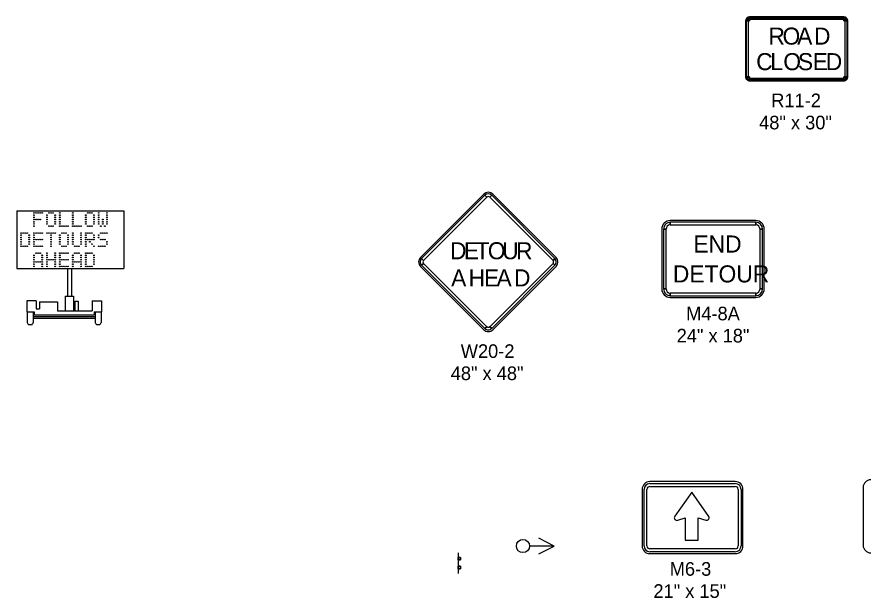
# Model space of a CAD drawing. Extents: x 10133 to 81668, y 6132 to 11018.
# Drawn here: x 10465.2 to 10961.7, y 6745 to 7086.2 of the extents above; entities that cross this region are included whole.
import ezdxf

# ---------------------------------------------------------------- set-up
doc = ezdxf.new("R2010")
doc.units = 0
for name, color, linetype in [('Level 1', 7, 'Continuous'), ('Level 10', 7, 'Continuous'), ('Level 5', 7, 'Continuous'), ('Level 9', 7, 'Continuous')]:
    doc.layers.add(name, color=color, linetype=linetype)

msp = doc.modelspace()

# ---------------------------------------------------------------- linework, layer by layer
at = {"layer": 'Level 1'}
for p, q in [((10780.56, 6775.55), (10771.42, 6780.12)), ((10780.56, 6775.55), (10766.05, 6775.55)), ((10771.42, 6770.98), (10780.56, 6775.55))]:
    msp.add_line(p, q, dxfattribs=at)
msp.add_circle((10762.18, 6775.55), 3.87, dxfattribs=at)
at = {"layer": 'Level 10'}
for p, q in [((10898.75, 6966.63), (10848.64, 6966.63)), ((10843.63, 6961.62), (10843.63, 6926.54)), ((10844.63, 6961.62), (10844.63, 6926.54)), ((10846.14, 6961.62), (10844.63, 6961.62)), ((10844.63, 6961.62), (10846.14, 6961.62)), ((10846.14, 6926.54), (10846.14, 6961.62)), ((10848.64, 6964.12), (10848.64, 6965.62)), ((10898.75, 6965.62), (10848.64, 6965.62)), ((10848.64, 6965.62), (10848.64, 6964.12)), ((10848.64, 6964.12), (10898.75, 6964.12)), ((10898.75, 6964.12), (10898.75, 6965.62)), ((10898.75, 6965.62), (10898.75, 6964.12)), ((10901.25, 6961.62), (10902.76, 6961.62)), ((10901.25, 6961.62), (10901.25, 6926.54)), ((10902.76, 6961.62), (10901.25, 6961.62)), ((10902.76, 6926.54), (10902.76, 6961.62)), ((10903.76, 6926.54), (10903.76, 6961.62)), ((10844.63, 6926.54), (10846.14, 6926.54)), ((10846.14, 6926.54), (10844.63, 6926.54)), ((10898.75, 6924.03), (10848.64, 6924.03)), ((10848.64, 6924.03), (10848.64, 6922.53)), ((10848.64, 6922.53), (10848.64, 6924.03)), ((10848.64, 6922.53), (10898.75, 6922.53)), ((10898.75, 6924.03), (10898.75, 6922.53)), ((10898.75, 6922.53), (10898.75, 6924.03)), ((10901.25, 6926.54), (10902.76, 6926.54)), ((10902.76, 6926.54), (10901.25, 6926.54)), ((10848.64, 6921.53), (10898.75, 6921.53)), ((10886.77, 6813.35), (10836.6, 6813.35)), ((10832.09, 6808.84), (10832.09, 6775.59)), ((10833.23, 6775.59), (10833.23, 6808.84)), ((10834.92, 6775.59), (10834.92, 6808.84)), ((10836.61, 6812.23), (10886.78, 6812.23)), ((10836.61, 6810.54), (10886.78, 6810.54)), ((10888.47, 6808.84), (10888.47, 6775.59)), ((10890.16, 6808.84), (10890.16, 6775.59)), ((10891.28, 6775.59), (10891.28, 6808.84)), ((10961.75, 6809.89), (10961.75, 6776.11)), ((10861.17, 6807.27), (10851.25, 6793)), ((10871.26, 6792.83), (10861.17, 6807.27)), ((10852.99, 6790.74), (10857.34, 6792.13)), ((10857.34, 6792.13), (10857.34, 6779.08)), ((10865, 6791.96), (10865, 6792.13)), ((10865, 6792.13), (10869.52, 6790.74)), ((10865, 6778.91), (10865, 6791.96)), ((10857.34, 6779.08), (10857.34, 6778.91)), ((10857.34, 6778.91), (10865, 6778.91)), ((10886.78, 6773.89), (10836.61, 6773.89)), ((10836.6, 6771.08), (10886.77, 6771.08)), ((10886.78, 6772.2), (10836.61, 6772.2))]:
    msp.add_line(p, q, dxfattribs=at)
for centre, radius, start, end in [((10848.64, 6961.62), 5.01, 90, 180), ((10898.75, 6961.62), 5.01, 0, 90), ((10848.64, 6961.62), 4.01, 90, 180), ((10848.64, 6961.62), 2.51, 90, 180), ((10898.75, 6961.62), 4.01, 0, 90), ((10898.75, 6961.62), 2.51, 0, 90), ((10848.64, 6926.54), 5.01, 180, 270), ((10848.64, 6926.54), 4.01, 180, 270), ((10848.64, 6926.54), 2.51, 180, 270), ((10898.75, 6926.54), 2.51, 270, 0), ((10898.75, 6926.54), 4.01, 270, 360), ((10898.75, 6926.54), 5.01, 270, 0), ((10836.6, 6808.84), 4.51, 90, 180), ((10886.77, 6808.84), 4.51, 360, 90), ((10966.33, 6809.89), 4.58, 90, 180), ((10836.61, 6808.84), 3.38, 90, 180), ((10836.61, 6808.84), 1.69, 90, 180), ((10886.78, 6808.84), 3.38, 0, 90), ((10886.78, 6808.84), 1.69, 0, 90), ((10852.46, 6792.13), 1.49, 144.2678, 290.8693), ((10869.91, 6792.18), 1.5, 254.9696, 25.4193), ((10836.6, 6775.59), 4.51, 180, 270), ((10836.61, 6775.59), 3.38, 180, 270), ((10836.61, 6775.59), 1.69, 180, 270), ((10886.77, 6775.59), 4.51, 270, 0), ((10886.78, 6775.59), 3.38, 270, 0), ((10886.78, 6775.59), 1.69, 270, 0), ((10966.33, 6776.11), 4.58, 180, 270)]:
    msp.add_arc(centre, radius, start, end, dxfattribs=at)
at = {"layer": 'Level 5'}
for p, q in [((10895.13, 7083.82), (10895.13, 7086.16)), ((10950.45, 7086.16), (10950.45, 7083.82)), ((10892.79, 7083.82), (10895.13, 7083.82)), ((10893.42, 7083.82), (10894.35, 7083.82)), ((10895.13, 7084.6), (10895.13, 7085.54)), ((10950.45, 7085.54), (10950.45, 7084.6)), ((10950.45, 7083.82), (10952.79, 7083.82)), ((10951.23, 7083.82), (10952.17, 7083.82)), ((10895.13, 7051.01), (10892.79, 7051.01)), ((10894.35, 7051.01), (10893.42, 7051.01)), ((10895.13, 7048.66), (10895.13, 7051.01)), ((10952.79, 7051.01), (10950.45, 7051.01)), ((10950.45, 7051.01), (10950.45, 7048.66)), ((10952.17, 7051.01), (10951.23, 7051.01)), ((10895.13, 7049.29), (10895.13, 7050.23)), ((10950.45, 7050.23), (10950.45, 7049.29)), ((10739.16, 6982.12), (10702.04, 6944.99)), ((10739.82, 6981.45), (10740.93, 6980.35)), ((10742.69, 6980.35), (10743.8, 6981.45)), ((10781.59, 6944.99), (10744.46, 6982.12)), ((10703.8, 6943.23), (10702.7, 6944.33)), ((10780.92, 6944.33), (10779.82, 6943.23)), ((10702.04, 6939.69), (10739.16, 6902.57)), ((10702.7, 6940.35), (10703.8, 6941.46)), ((10744.46, 6902.57), (10781.59, 6939.69)), ((10779.82, 6941.46), (10780.92, 6940.35)), ((10740.93, 6904.33), (10739.82, 6903.23)), ((10743.8, 6903.23), (10742.69, 6904.33))]:
    msp.add_line(p, q, dxfattribs=at)
for points in [[(10895.13, 7048.66), (10950.45, 7048.66), (10950.45, 7051.01), (10952.79, 7051.01), (10952.79, 7083.82), (10950.45, 7083.82), (10950.45, 7086.16), (10895.13, 7086.16), (10895.13, 7083.82), (10892.79, 7083.82), (10892.79, 7051.01), (10895.13, 7051.01), (10895.13, 7048.66)], [(10894.35, 7083.82), (10894.35, 7051.01), (10893.42, 7051.01), (10893.42, 7083.82), (10894.35, 7083.82)], [(10950.45, 7084.6), (10895.13, 7084.6), (10895.13, 7085.54), (10950.45, 7085.54), (10950.45, 7084.6)], [(10951.23, 7051.01), (10951.23, 7083.82), (10952.17, 7083.82), (10952.17, 7051.01), (10951.23, 7051.01)], [(10895.13, 7050.23), (10950.45, 7050.23), (10950.45, 7049.29), (10895.13, 7049.29), (10895.13, 7050.23)], [(10739.82, 6981.45), (10702.7, 6944.33), (10703.8, 6943.23), (10740.93, 6980.35), (10739.82, 6981.45)], [(10780.92, 6944.33), (10743.8, 6981.45), (10742.69, 6980.35), (10779.82, 6943.23), (10780.92, 6944.33)], [(10702.7, 6940.35), (10739.82, 6903.23), (10740.93, 6904.33), (10703.8, 6941.46), (10702.7, 6940.35)], [(10743.8, 6903.23), (10780.92, 6940.35), (10779.82, 6941.46), (10742.69, 6904.33), (10743.8, 6903.23)]]:
    msp.add_lwpolyline(points, close=True, dxfattribs=at)
for centre, radius, start, end in [((10895.13, 7083.82), 2.34, 90.0002, 179.9998), ((10950.45, 7083.82), 2.34, 360, 90.0002), ((10895.13, 7083.82), 1.72, 90.0002, 179.9998), ((10895.13, 7083.82), 0.781, 90.0002, 179.9998), ((10950.45, 7083.82), 1.72, 360, 90.0002), ((10950.45, 7083.82), 0.781, 360, 90.0002), ((10895.13, 7051.01), 2.34, 179.9998, 270.0001), ((10895.13, 7051.01), 1.72, 179.9998, 270.0001), ((10895.13, 7051.01), 0.781, 179.9998, 270.0001), ((10950.45, 7051.01), 2.34, 270.0001, 0.0003), ((10950.45, 7051.01), 1.72, 270.0001, 0.0003), ((10950.45, 7051.01), 0.781, 270.0001, 0.0003), ((10741.81, 6979.46), 3.75, 45, 134.9997), ((10741.81, 6979.46), 2.81, 45, 134.9997), ((10741.81, 6979.46), 1.25, 45, 134.9997), ((10704.69, 6942.34), 3.75, 134.9997, 225), ((10704.69, 6942.34), 2.81, 134.9997, 225), ((10704.69, 6942.34), 1.25, 134.9997, 225), ((10778.93, 6942.34), 1.25, 315.0002, 44.9998), ((10778.93, 6942.34), 2.81, 315.0002, 44.9998), ((10778.93, 6942.34), 3.75, 315.0002, 44.9998), ((10741.81, 6905.22), 3.75, 225, 315.0002), ((10741.81, 6905.22), 2.81, 225, 315.0002), ((10741.81, 6905.22), 1.25, 225, 315.0002)]:
    msp.add_arc(centre, radius, start, end, dxfattribs=at)
at = {"layer": 'Level 9'}
for p, q in [((10465.21, 6972.37), (10465.21, 6938.45)), ((10465.21, 6972.37), (10528.02, 6972.37)), ((10528.02, 6972.37), (10528.02, 6938.45)), ((10465.21, 6938.45), (10528.02, 6938.45)), ((10494.94, 6938.45), (10494.94, 6922.2)), ((10497.23, 6938.45), (10497.23, 6922.2)), ((10493.5, 6922.2), (10498.47, 6922.2)), ((10493.5, 6922.2), (10493.5, 6913.65)), ((10498.47, 6922.2), (10498.47, 6913.65)), ((10476.52, 6919.43), (10471.07, 6919.43)), ((10471.07, 6919.43), (10471.07, 6913.7)), ((10476.52, 6919.43), (10476.52, 6914.75)), ((10478.4, 6918.95), (10478.4, 6914.75)), ((10509.38, 6919.43), (10509.38, 6913.65)), ((10509.38, 6919.43), (10514.83, 6919.43)), ((10514.83, 6919.43), (10514.83, 6913.06)), ((10471.07, 6913.7), (10471.07, 6913.06)), ((10471.07, 6913.06), (10475.39, 6913.06)), ((10471.29, 6913.06), (10471.29, 6906.77)), ((10474.79, 6913.06), (10474.79, 6906.77)), ((10475.39, 6913.06), (10475.39, 6911.32)), ((10476.52, 6914.75), (10478.4, 6914.75)), ((10488.97, 6913.65), (10509.38, 6913.65)), ((10510.53, 6913.06), (10510.53, 6911.32)), ((10511.13, 6913.06), (10511.13, 6906.77)), ((10514.63, 6913.06), (10514.63, 6906.77)), ((10474.79, 6910.26), (10511.13, 6910.26)), ((10474.79, 6909.29), (10511.13, 6909.29)), ((10475.39, 6911.32), (10510.53, 6911.32)), ((10472.48, 6905.59), (10473.6, 6905.59)), ((10512.32, 6905.59), (10513.43, 6905.59)), ((10724.2, 6771.5), (10724.2, 6759.5)), ((10724.2, 6768.82), (10724.2, 6767.42)), ((10724.2, 6763.68), (10724.2, 6762.27))]:
    msp.add_line(p, q, dxfattribs=at)
for points in [[(10478.4, 6918.95), (10488.97, 6918.95), (10488.97, 6913.65)], [(10499.38, 6913.65), (10499.38, 6919.28), (10501.11, 6919.28), (10501.11, 6913.65)], [(10510.53, 6913.06), (10514.83, 6913.06)], [(10724.2, 6767.42), (10725.6, 6767.42), (10725.6, 6768.82), (10724.2, 6768.82)], [(10724.2, 6762.27), (10725.6, 6762.27), (10725.6, 6763.68), (10724.2, 6763.68)]]:
    msp.add_lwpolyline(points, dxfattribs=at)
for points in [[(10724.2, 6767.42), (10724.2, 6768.82), (10725.6, 6768.82), (10725.6, 6767.42)], [(10724.2, 6762.27), (10724.2, 6763.68), (10725.6, 6763.68), (10725.6, 6762.27)]]:
    msp.add_lwpolyline(points, close=True, dxfattribs=at)
for centre in [(10475.22, 6971.11), (10475.22, 6969.81), (10475.22, 6968.51), (10475.22, 6967.21), (10476.42, 6971.11), (10476.42, 6967.21), (10477.62, 6971.11), (10477.62, 6967.21), (10478.82, 6971.11), (10478.82, 6967.21), (10480.02, 6971.11), (10482.82, 6969.81), (10482.82, 6968.51), (10482.82, 6967.21), (10484.02, 6971.11), (10485.22, 6971.11), (10486.42, 6971.11), (10487.62, 6969.81), (10487.62, 6968.51), (10487.62, 6967.21), (10490.42, 6971.11), (10490.42, 6969.81), (10490.42, 6968.51), (10490.42, 6967.21), (10498.02, 6971.11), (10498.02, 6969.81), (10498.02, 6968.51), (10498.02, 6967.21), (10505.62, 6969.81), (10505.62, 6968.51), (10505.62, 6967.21), (10506.82, 6971.11), (10508.02, 6971.11), (10509.22, 6971.11), (10510.42, 6969.81), (10510.42, 6968.51), (10510.42, 6967.21), (10513.22, 6971.11), (10513.22, 6969.81), (10513.22, 6968.51), (10513.22, 6967.21), (10515.62, 6967.21), (10518.02, 6971.11), (10518.02, 6969.81), (10518.02, 6968.51), (10518.02, 6967.21), (10475.22, 6965.91), (10475.22, 6964.61), (10475.22, 6963.31), (10482.82, 6965.91), (10482.82, 6964.61), (10484.02, 6963.31), (10485.22, 6963.31), (10486.42, 6963.31), (10487.62, 6965.91), (10487.62, 6964.61), (10490.42, 6965.91), (10490.42, 6964.61), (10490.42, 6963.31), (10491.62, 6963.31), (10492.82, 6963.31), (10494.02, 6963.31), (10495.22, 6963.31), (10498.02, 6965.91), (10498.02, 6964.61), (10498.02, 6963.31), (10499.22, 6963.31), (10500.42, 6963.31), (10501.62, 6963.31), (10502.82, 6963.31), (10505.62, 6965.91), (10505.62, 6964.61), (10506.82, 6963.31), (10508.02, 6963.31), (10509.22, 6963.31), (10510.42, 6965.91), (10510.42, 6964.61), (10513.22, 6965.91), (10513.22, 6964.61), (10514.42, 6963.31), (10515.62, 6965.91), (10515.62, 6964.61), (10516.82, 6963.31), (10518.02, 6965.91), (10518.02, 6964.61), (10467.62, 6959.31), (10467.62, 6958.01), (10467.62, 6956.71), (10468.82, 6959.31), (10470.02, 6959.31), (10471.22, 6959.31), (10472.42, 6958.01), (10472.42, 6956.71), (10475.22, 6959.31), (10475.22, 6958.01), (10475.22, 6956.71), (10476.42, 6959.31), (10477.62, 6959.31), (10478.82, 6959.31), (10480.02, 6959.31), (10482.82, 6959.31), (10484.02, 6959.31), (10485.22, 6959.31), (10485.22, 6958.01), (10485.22, 6956.71), (10486.42, 6959.31), (10487.62, 6959.31), (10490.42, 6958.01), (10490.42, 6956.71), (10491.62, 6959.31), (10492.82, 6959.31), (10494.02, 6959.31), (10495.22, 6958.01), (10495.22, 6956.71), (10498.02, 6959.31), (10498.02, 6958.01), (10498.02, 6956.71), (10502.82, 6959.31), (10502.82, 6958.01), (10502.82, 6956.71), (10505.62, 6959.31), (10505.62, 6958.01), (10505.62, 6956.71), (10506.82, 6959.31), (10508.02, 6959.31), (10509.22, 6959.31), (10510.42, 6958.01), (10510.42, 6956.71), (10513.22, 6958.01), (10513.22, 6956.71), (10514.42, 6959.31), (10515.62, 6959.31), (10516.82, 6959.31), (10518.02, 6959.31), (10467.62, 6955.41), (10467.62, 6954.11), (10467.62, 6952.81), (10467.62, 6951.51), (10468.82, 6951.51), (10470.02, 6951.51), (10471.22, 6951.51), (10472.42, 6955.41), (10472.42, 6954.11), (10472.42, 6952.81), (10475.22, 6955.41), (10475.22, 6954.11), (10475.22, 6952.81), (10475.22, 6951.51), (10476.42, 6955.41), (10476.42, 6951.51), (10477.62, 6955.41), (10477.62, 6951.51), (10478.82, 6955.41), (10478.82, 6951.51), (10480.02, 6955.41), (10480.02, 6951.51), (10485.22, 6955.41), (10485.22, 6954.11), (10485.22, 6952.81), (10485.22, 6951.51), (10490.42, 6955.41), (10490.42, 6954.11), (10490.42, 6952.81), (10491.62, 6951.51), (10492.82, 6951.51), (10494.02, 6951.51), (10495.22, 6955.41), (10495.22, 6954.11), (10495.22, 6952.81), (10498.02, 6955.41), (10498.02, 6954.11), (10498.02, 6952.81), (10499.22, 6951.51), (10500.42, 6951.51), (10501.62, 6951.51), (10502.82, 6955.41), (10502.82, 6954.11), (10502.82, 6952.81), (10505.62, 6955.41), (10505.62, 6954.11), (10505.62, 6952.81), (10505.62, 6951.51), (10506.82, 6955.41), (10508.02, 6955.41), (10508.02, 6954.11), (10509.22, 6955.41), (10509.22, 6952.81), (10510.42, 6955.41), (10510.42, 6951.51), (10513.22, 6951.51), (10514.42, 6955.41), (10514.42, 6951.51), (10515.62, 6955.41), (10515.62, 6951.51), (10516.82, 6955.41), (10516.82, 6951.51), (10518.02, 6954.11), (10518.02, 6952.81), (10476.42, 6947.51), (10477.62, 6947.51), (10478.82, 6947.51), (10482.82, 6947.51), (10487.62, 6947.51), (10490.42, 6947.51), (10491.62, 6947.51), (10492.82, 6947.51), (10494.02, 6947.51), (10495.22, 6947.51), (10499.22, 6947.51), (10500.42, 6947.51), (10501.62, 6947.51), (10505.62, 6947.51), (10506.82, 6947.51), (10508.02, 6947.51), (10509.22, 6947.51), (10475.22, 6946.21), (10475.22, 6944.91), (10475.22, 6943.61), (10475.22, 6942.31), (10476.42, 6942.31), (10477.62, 6942.31), (10478.82, 6942.31), (10480.02, 6946.21), (10480.02, 6944.91), (10480.02, 6943.61), (10480.02, 6942.31), (10482.82, 6946.21), (10482.82, 6944.91), (10482.82, 6943.61), (10482.82, 6942.31), (10484.02, 6943.61), (10485.22, 6943.61), (10486.42, 6943.61), (10487.62, 6946.21), (10487.62, 6944.91), (10487.62, 6943.61), (10487.62, 6942.31), (10490.42, 6946.21), (10490.42, 6944.91), (10490.42, 6943.61), (10490.42, 6942.31), (10491.62, 6943.61), (10492.82, 6943.61), (10494.02, 6943.61), (10495.22, 6943.61), (10498.02, 6946.21), (10498.02, 6944.91), (10498.02, 6943.61), (10498.02, 6942.31), (10499.22, 6942.31), (10500.42, 6942.31), (10501.62, 6942.31), (10502.82, 6946.21), (10502.82, 6944.91), (10502.82, 6943.61), (10502.82, 6942.31), (10505.62, 6946.21), (10505.62, 6944.91), (10505.62, 6943.61), (10505.62, 6942.31), (10510.42, 6946.21), (10510.42, 6944.91), (10510.42, 6943.61), (10510.42, 6942.31), (10475.22, 6941.01), (10475.22, 6939.71), (10480.02, 6941.01), (10480.02, 6939.71), (10482.82, 6941.01), (10482.82, 6939.71), (10487.62, 6941.01), (10487.62, 6939.71), (10490.42, 6941.01), (10490.42, 6939.71), (10491.62, 6939.71), (10492.82, 6939.71), (10494.02, 6939.71), (10495.22, 6939.71), (10498.02, 6941.01), (10498.02, 6939.71), (10502.82, 6941.01), (10502.82, 6939.71), (10505.62, 6941.01), (10505.62, 6939.71), (10506.82, 6939.71), (10508.02, 6939.71), (10509.22, 6939.71), (10510.42, 6941.01)]:
    msp.add_circle(centre, 0.2, dxfattribs=at)
for centre, major_axis, start_param, end_param in [((10472.48, 6906.77), (-1.19, 0), 0, 1.570796), ((10473.6, 6906.77), (1.19, 0), 4.712389, 6.283185), ((10512.32, 6906.77), (-1.19, 0), 0, 1.570796), ((10513.43, 6906.77), (1.19, 0), 4.712389, 6.283185)]:
    msp.add_ellipse(centre, major_axis=major_axis, ratio=0.989241, start_param=start_param, end_param=end_param, dxfattribs=at)

# ---------------------------------------------------------------- texts
at = {"layer": 'Level 10'}
for s, p in [('END', (10862.17, 6947.84)), ('DETOUR', (10850.12, 6930.3))]:
    msp.add_text(s, height=10.021, dxfattribs=at).set_placement(p)
at = {"layer": 'Level 5'}
for s, height, p in [('R', 10, (10906.23, 7069.91)), ('O', 10, (10914.48, 7069.91)), ('A', 10, (10923.05, 7069.91)), ('D', 10, (10932.95, 7069.91)), ('C', 10, (10899.02, 7054.91)), ('L', 10, (10907.29, 7054.91)), ('O', 10, (10914.94, 7054.91)), ('S', 10, (10923.53, 7054.91)), ('E', 10, (10932.19, 7054.91)), ('D', 10, (10939.84, 7054.91)), ('R11-2', 8, (10907.87, 7033.16)), ('48" x 30"', 8, (10900.76, 7020.16)), ('D', 10, (10719.35, 6943.9)), ('E', 10, (10727.47, 6943.9)), ('T', 10, (10734.32, 6943.9)), ('O', 10, (10741.54, 6943.9)), ('U', 10, (10749.97, 6943.9)), ('R', 10, (10758.1, 6943.9)), ('A', 10, (10720.01, 6927.97)), ('H', 10, (10730.25, 6927.97)), ('E', 10, (10739.31, 6927.97)), ('A', 10, (10746.65, 6927.97)), ('D', 10, (10756.89, 6927.97)), ('M4-8A', 8, (10857.92, 6908.05)), ('24" x 18"', 8, (10852.36, 6895.05)), ('W20-2', 8, (10725.65, 6885.97)), ('48" x 48"', 8, (10719.78, 6872.97)), ('M6-3', 8, (10848.28, 6758.12)), ('21" x 15"', 8, (10838.72, 6745.12))]:
    msp.add_text(s, height=height, dxfattribs=at).set_placement(p)

doc.saveas('drawing.dxf')
